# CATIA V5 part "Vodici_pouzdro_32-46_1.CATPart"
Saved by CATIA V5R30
Part number: Vodici_pouzdro_32-46_1
Definition: E 1100_32-46_1
Nomenclature: E 1100_32-46_1
Source: Unknown
Description: PART--DESC
Bounding box of the stored display mesh (mm): x -210.3 to -163.7, y 113.7 to 160.3, z -101 to -46
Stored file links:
  E:\Bakalarka\Model\Forma_v7\Vodici_pouzdro_32-46_1.CATPart
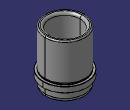
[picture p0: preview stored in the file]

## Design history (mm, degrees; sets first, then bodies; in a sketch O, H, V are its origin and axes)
Body1 "MANIFOLD_SOLID_BREP #3922" (main body)
  Solid1: solid without history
